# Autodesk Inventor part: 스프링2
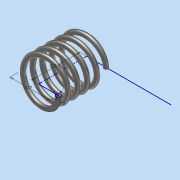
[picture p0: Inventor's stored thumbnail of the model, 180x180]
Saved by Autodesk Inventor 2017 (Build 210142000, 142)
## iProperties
Part Number: 스프링2
Material: 스테인레스 스틸
Document SubType Name: Modeling
Designer: MRC
Density: 8 g/cm^3
Appearance: 반연마
Mass: 6.57569 g
Surface Area: 16.7185 cm^2
Volume: 0.821961 cm^3
Author: MRC
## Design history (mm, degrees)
sketch "스케치1"
  geometry: L1 (0, 0)-(0, 20.5); L2 (0, 0)-(8.5, 0); L3 (0, 20.5)-(36.027, 20.5); C1 r 1 at (8.5, 0)
  constraints: 6 end point, 2 horizontal, 1 centre point, 1 coincident, 1 vertical
  dimensions: "d0" = 20.5 distance of L1.start L1.end (derived); "d2" = 2 diameter of C1; "d3" = 17 diameter of L2.end L1
feature "코일1" pitch "d4" = 10; turns "d6" = 5; dims "d5" = 20.5 (= d0), "d7" = 0, angle "d8" = 90 deg, angle "d9" = 90 deg, "d10" = 0, "d11" = 0
sketch "스케치2"
  geometry: L1 (20.5, 10)-(0, 10); L2 (0, 10)-(0, -10); L3 (0, -10)-(20.5, -10); L4 (20.5, -10)-(20.5, 10); 2 further points
  constraints: 8 end point, 2 parallel, 1 coincident, 1 horizontal, 1 midpoint, 1 perpendicular
  dimensions: "d12" = 20 distance of L3.end L1.start; "d13" = 20.5 distance of L2.end L3.end (= d0)
extrude "돌출1" sketch "스케치2" stored distance "d14" = 0; taper "d15" = 0 deg
node "솔리드1"
